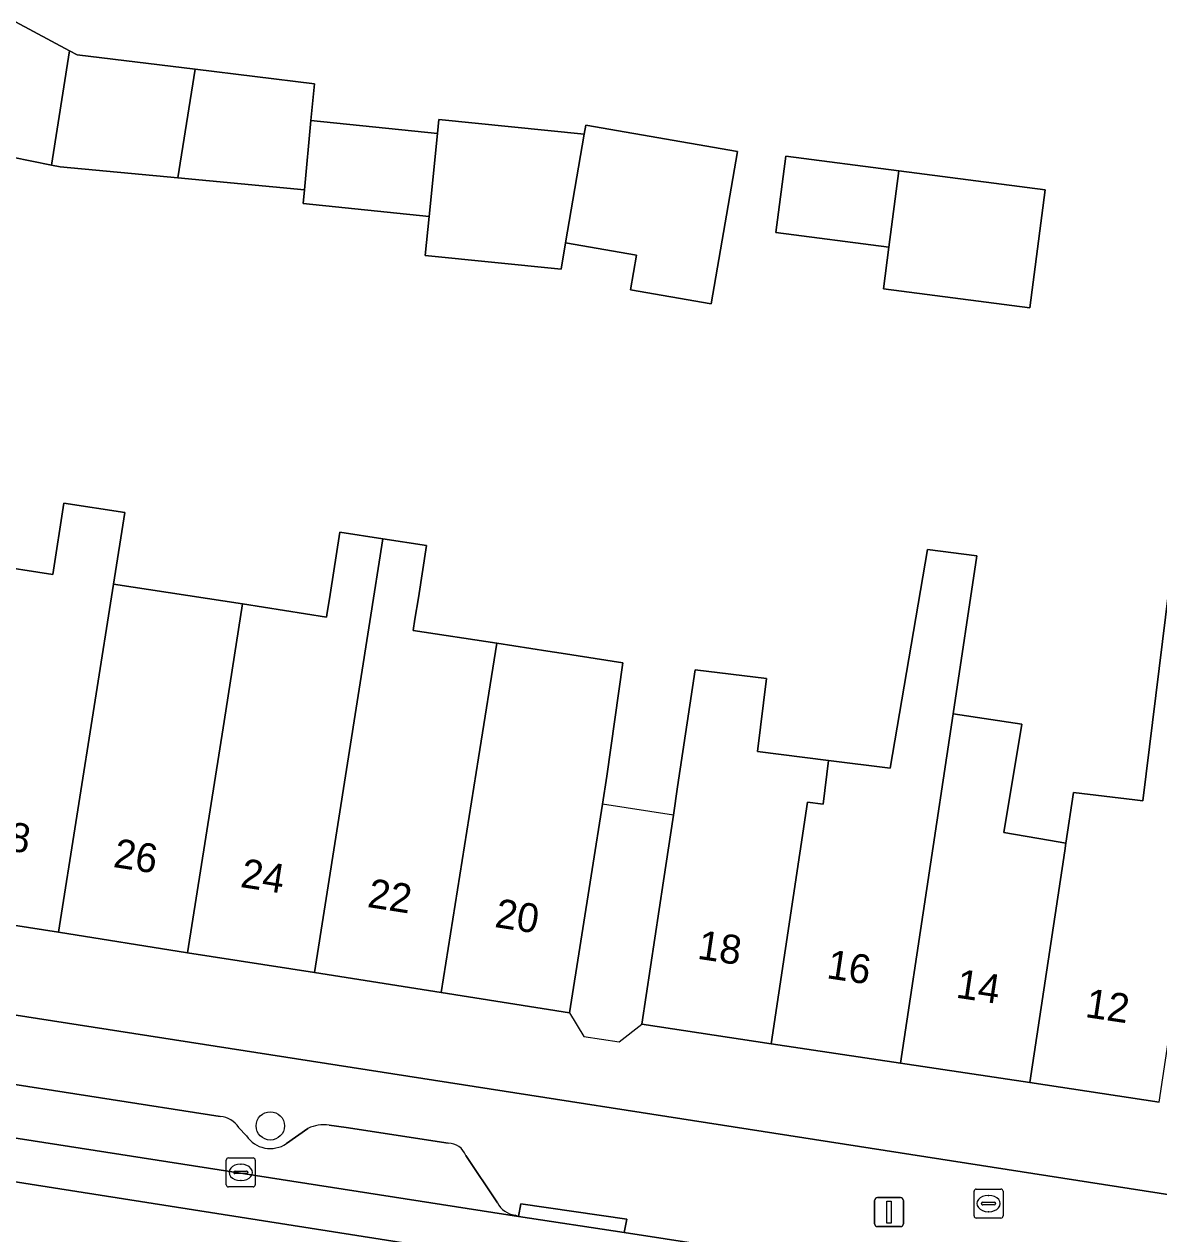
# Model space of a CAD drawing. Extents: x 162172 to 163187, y 382874 to 383685.
# Drawn here: x 162633.67 to 162672.8, y 383331.69 to 383373.42 of the extents above; entities that cross this region are included whole.
import ezdxf

# ---------------------------------------------------------------- set-up
doc = ezdxf.new("R2010")
doc.units = 0
for name, color, linetype in [('IMGEO_Boom', 7, 'Continuous'), ('IMGEO_Brandkraan', 7, 'Continuous'), ('IMGEO_Erf', 7, 'Continuous'), ('IMGEO_Kolk', 7, 'Continuous'), ('IMGEO_Lichtmast', 7, 'Continuous'), ('IMGEO_Pand', 7, 'Continuous'), ('IMGEO_Pand_nummerreeks', 7, 'Continuous'), ('IMGEO_Pand_overbouw', 7, 'Continuous'), ('IMGEO_Parkeervlak_open', 7, 'Continuous'), ('IMGEO_Rijbaan_lokaal_gesloten', 7, 'Continuous'), ('IMGEO_Voetpad_open', 7, 'Continuous')]:
    doc.layers.add(name, color=color, linetype=linetype)

msp = doc.modelspace()

# ---------------------------------------------------------------- linework, layer by layer
at = {"layer": 'IMGEO_Boom'}
msp.add_circle((162642.154, 383335.41), 0.489, dxfattribs=at)
at = {"layer": 'IMGEO_Brandkraan'}
for p, q in [((162666.424, 383332.304), (162666.424, 383333.156)), ((162666.499, 383333.23), (162667.351, 383333.23)), ((162667.425, 383333.156), (162667.425, 383332.304)), ((162666.683, 383332.724), (162666.683, 383332.736)), ((162667.121, 383332.687), (162666.723, 383332.687)), ((162666.726, 383332.773), (162667.124, 383332.773)), ((162666.912, 383333.01), (162666.937, 383333.01)), ((162667.167, 383332.736), (162667.167, 383332.724)), ((162667.351, 383332.23), (162666.499, 383332.23)), ((162666.935, 383332.45), (162666.91, 383332.45))]:
    msp.add_line(p, q, dxfattribs=at)
for points in [[(162666.424, 383332.304), (162666.424, 383333.156)], [(162666.499, 383333.23), (162667.351, 383333.23)], [(162667.425, 383333.156), (162667.425, 383332.304)], [(162667.351, 383332.23), (162666.499, 383332.23)]]:
    msp.add_lwpolyline(points, dxfattribs=at)
for centre, radius, start, end in [((162666.501, 383333.154), 0.0765, 91.552, 178.448), ((162666.501, 383333.154), 0.0765, 91.552, 178.448), ((162667.349, 383333.154), 0.0765, 1.552, 88.448), ((162667.349, 383333.154), 0.0765, 1.552, 88.448), ((162666.723, 383332.733), 0.0403, 85.8775, 175.7526), ((162666.72, 383332.723), 0.0366, 178.938, 274.7102), ((162667.124, 383332.73), 0.043, 264.8664, 352.4533), ((162667.128, 383332.735), 0.0386, 1.7309, 96.639), ((162666.501, 383332.306), 0.0765, 181.552, 268.448), ((162666.501, 383332.306), 0.0765, 181.552, 268.448), ((162667.349, 383332.306), 0.0765, 271.552, 358.448), ((162667.349, 383332.306), 0.0765, 271.552, 358.448)]:
    msp.add_arc(centre, radius, start, end, dxfattribs=at)
for centre, major_axis, ratio, start_param, end_param in [((162666.911, 383332.73), (-0.387, 0.002), 0.722429, 4.712389, 7.853982), ((162666.936, 383332.73), (-0.39, 0.002), 0.717154, 1.570796, 4.712389)]:
    msp.add_ellipse(centre, major_axis=major_axis, ratio=ratio, start_param=start_param, end_param=end_param, dxfattribs=at)
at = {"layer": 'IMGEO_Erf'}
for points in [[(162657.355, 383363.773), (162654.579, 383364.252), (162654.786, 383365.449), (162652.337, 383365.872), (162652.18, 383364.963), (162647.493, 383365.442), (162647.63, 383366.787), (162643.29, 383367.231), (162643.334, 383367.707), (162638.969, 383368.115), (162634.911, 383368.495), (162634.612, 383368.556), (162630.529, 383369.385), (162631.35, 383374.589), (162635.235, 383372.503), (162635.493, 383372.364), (162639.563, 383371.863), (162643.675, 383371.357), (162643.557, 383370.091), (162647.922, 383369.645), (162647.972, 383370.133), (162652.984, 383369.621), (162653.038, 383369.931), (162658.262, 383369.029)], [(162668.352, 383363.634), (162663.296, 383364.291), (162663.483, 383365.725), (162659.593, 383366.23), (162659.935, 383368.867), (162663.826, 383368.361), (162668.881, 383367.704)]]:
    msp.add_lwpolyline(points, close=True, dxfattribs=at)
for points in [[(162632.43, 383354.782), (162634.653, 383354.438), (162635.034, 383356.898), (162637.141, 383356.572), (162636.75, 383354.103), (162641.194, 383353.415), (162644.093, 383352.966), (162644.104, 383353.036), (162644.216, 383353.742), (162644.555, 383355.896), (162646.035, 383355.667), (162647.545, 383355.433), (162647.261, 383353.63), (162647.144, 383352.888), (162647.083, 383352.503), (162649.963, 383352.058), (162651.73, 383351.784), (162652.182, 383351.714), (162654.308, 383351.385), (162653.761, 383347.48), (162653.608, 383346.505), (162653.253, 383344.252), (162652.476, 383339.312), (162648.053, 383340.008), (162643.675, 383340.698), (162639.301, 383341.386), (162634.846, 383342.088), (162630.546, 383342.765)], [(162672.811, 383336.231), (162668.35, 383336.902), (162663.891, 383337.573), (162659.431, 383338.243), (162654.971, 383338.914), (162655.715, 383343.859), (162656.055, 383346.125), (162656.202, 383347.105), (162656.81, 383351.144), (162659.272, 383350.84), (162658.96, 383348.322), (162661.408, 383348.019), (162663.53, 383347.756), (162664.816, 383355.293), (162666.525, 383355.081), (162665.704, 383349.623), (162668.072, 383349.267), (162667.447, 383345.529), (162668.997, 383345.262), (162669.592, 383345.16), (162669.856, 383346.915), (162671.969, 383346.653), (162672.244, 383346.619), (162673.262, 383354.819)], [(162625.697, 383340.429), (162681.225, 383331.781)]]:
    msp.add_lwpolyline(points, dxfattribs=at)
at = {"layer": 'IMGEO_Kolk'}
for p, q in [((162640.636, 383333.381), (162640.636, 383334.233)), ((162640.711, 383334.307), (162641.563, 383334.307)), ((162641.124, 383334.087), (162641.149, 383334.087)), ((162641.637, 383334.233), (162641.637, 383333.381)), ((162640.895, 383333.801), (162640.895, 383333.813)), ((162641.333, 383333.764), (162640.935, 383333.764)), ((162640.938, 383333.85), (162641.336, 383333.85)), ((162641.147, 383333.527), (162641.122, 383333.527)), ((162641.379, 383333.813), (162641.379, 383333.801)), ((162641.563, 383333.307), (162640.711, 383333.307))]:
    msp.add_line(p, q, dxfattribs=at)
for points in [[(162640.636, 383333.381), (162640.636, 383334.233)], [(162640.711, 383334.307), (162641.563, 383334.307)], [(162641.637, 383334.233), (162641.637, 383333.381)], [(162641.563, 383333.307), (162640.711, 383333.307)]]:
    msp.add_lwpolyline(points, dxfattribs=at)
for centre, radius, start, end in [((162640.713, 383334.231), 0.0765, 91.552, 178.448), ((162640.713, 383334.231), 0.0765, 91.552, 178.448), ((162641.561, 383334.231), 0.0765, 1.552, 88.448), ((162641.561, 383334.231), 0.0765, 1.552, 88.448), ((162640.935, 383333.81), 0.0403, 85.8775, 175.7526), ((162640.932, 383333.8), 0.0366, 178.938, 274.7102), ((162641.336, 383333.807), 0.043, 264.8664, 352.4533), ((162641.34, 383333.812), 0.0386, 1.7309, 96.639), ((162640.713, 383333.383), 0.0765, 181.552, 268.448), ((162640.713, 383333.383), 0.0765, 181.552, 268.448), ((162641.561, 383333.383), 0.0765, 271.552, 358.448), ((162641.561, 383333.383), 0.0765, 271.552, 358.448)]:
    msp.add_arc(centre, radius, start, end, dxfattribs=at)
for centre, major_axis, ratio, start_param, end_param in [((162641.123, 383333.807), (-0.387, 0.002), 0.722429, 4.712389, 7.853982), ((162641.148, 383333.807), (-0.39, 0.002), 0.717154, 1.570796, 4.712389)]:
    msp.add_ellipse(centre, major_axis=major_axis, ratio=ratio, start_param=start_param, end_param=end_param, dxfattribs=at)
at = {"layer": 'IMGEO_Lichtmast'}
for p, q in [((162662.996, 383332.034), (162662.996, 383332.834)), ((162662.996, 383332.834), (162662.996, 383332.034)), ((162663.096, 383332.934), (162663.886, 383332.934)), ((162663.886, 383332.934), (162663.096, 383332.934)), ((162663.986, 383332.834), (162663.986, 383332.034)), ((162663.986, 383332.034), (162663.986, 383332.834)), ((162663.886, 383331.934), (162663.096, 383331.934)), ((162663.096, 383331.934), (162663.886, 383331.934))]:
    msp.add_line(p, q, dxfattribs=at)
msp.add_lwpolyline([(162663.416, 383332.809), (162663.566, 383332.809), (162663.566, 383332.059), (162663.416, 383332.059), (162663.416, 383332.809)], dxfattribs=at)
for centre, start, end in [((162663.096, 383332.834), 90, 180), ((162663.096, 383332.834), 90, 180), ((162663.886, 383332.834), 0, 90), ((162663.886, 383332.834), 360, 90), ((162663.096, 383332.034), 180, 270), ((162663.096, 383332.034), 180, 270), ((162663.886, 383332.034), 270, 0), ((162663.886, 383332.034), 270, 0)]:
    msp.add_arc(centre, 0.1, start, end, dxfattribs=at)
at = {"layer": 'IMGEO_Pand'}
for points in [[(162634.612, 383368.556), (162635.235, 383372.503), (162631.35, 383374.589), (162630.529, 383369.385)], [(162638.969, 383368.115), (162639.563, 383371.863), (162635.493, 383372.364), (162635.235, 383372.503), (162634.612, 383368.556), (162634.911, 383368.495)], [(162643.557, 383370.091), (162643.675, 383371.357), (162639.563, 383371.863), (162638.969, 383368.115), (162643.334, 383367.707)], [(162647.922, 383369.645), (162643.557, 383370.091), (162643.334, 383367.707), (162643.29, 383367.231), (162647.63, 383366.787)], [(162652.984, 383369.621), (162647.972, 383370.133), (162647.922, 383369.645), (162647.63, 383366.787), (162647.493, 383365.442), (162652.18, 383364.963), (162652.337, 383365.872)], [(162658.262, 383369.029), (162653.038, 383369.931), (162652.984, 383369.621), (162652.337, 383365.872), (162654.786, 383365.449), (162654.579, 383364.252), (162657.355, 383363.773)], [(162663.826, 383368.361), (162659.935, 383368.867), (162659.593, 383366.23), (162663.483, 383365.725)], [(162663.826, 383368.361), (162663.483, 383365.725), (162663.296, 383364.291), (162668.352, 383363.634), (162668.881, 383367.704)], [(162674.624, 383348.282), (162675.443, 383353.731), (162676.222, 383358.91), (162674.187, 383359.162), (162673.954, 383359.191), (162673.807, 383359.209), (162673.775, 383358.952), (162673.706, 383358.396), (162673.262, 383354.819), (162672.244, 383346.619), (162671.969, 383346.653), (162669.856, 383346.915), (162669.592, 383345.16), (162669.553, 383344.9), (162668.35, 383336.902), (162672.811, 383336.231)], [(162636.75, 383354.103), (162637.141, 383356.572), (162635.034, 383356.898), (162634.653, 383354.438), (162632.43, 383354.782), (162631.805, 383350.75), (162630.546, 383342.765), (162634.846, 383342.088)], [(162641.194, 383353.415), (162640.565, 383349.363), (162639.301, 383341.386), (162643.675, 383340.698), (162645.584, 383352.806), (162646.035, 383355.667), (162644.555, 383355.896), (162644.216, 383353.742), (162644.104, 383353.036), (162644.093, 383352.966)], [(162649.963, 383352.058), (162647.083, 383352.503), (162647.144, 383352.888), (162647.261, 383353.63), (162647.545, 383355.433), (162646.035, 383355.667), (162645.584, 383352.806), (162643.675, 383340.698), (162648.053, 383340.008), (162649.337, 383348.109)], [(162665.704, 383349.623), (162666.525, 383355.081), (162664.816, 383355.293), (162663.53, 383347.756), (162661.408, 383348.019), (162661.221, 383346.511), (162660.684, 383346.577), (162659.431, 383338.243), (162663.891, 383337.573)], [(162641.194, 383353.415), (162636.75, 383354.103), (162634.846, 383342.088), (162639.301, 383341.386), (162640.565, 383349.363)], [(162653.608, 383346.505), (162653.761, 383347.48), (162654.308, 383351.385), (162652.182, 383351.714), (162651.73, 383351.784), (162649.963, 383352.058), (162649.337, 383348.109), (162648.053, 383340.008), (162652.476, 383339.312), (162653.253, 383344.252)], [(162660.684, 383346.577), (162661.221, 383346.511), (162661.408, 383348.019), (162658.96, 383348.322), (162659.272, 383350.84), (162656.81, 383351.144), (162656.202, 383347.105), (162656.055, 383346.125), (162655.715, 383343.859), (162654.971, 383338.914), (162659.431, 383338.243)], [(162669.592, 383345.16), (162668.997, 383345.262), (162667.447, 383345.529), (162668.072, 383349.267), (162665.704, 383349.623), (162663.891, 383337.573), (162668.35, 383336.902), (162669.553, 383344.9)]]:
    msp.add_lwpolyline(points, close=True, dxfattribs=at)
at = {"layer": 'IMGEO_Pand_overbouw'}
msp.add_lwpolyline([(162655.715, 383343.859), (162656.055, 383346.125), (162653.608, 383346.505), (162653.253, 383344.252), (162652.476, 383339.312), (162652.967, 383338.498), (162654.186, 383338.306), (162654.971, 383338.914)], close=True, dxfattribs=at)
at = {"layer": 'IMGEO_Parkeervlak_open'}
for points in [[(162613.69, 383338.058), (162650.713, 383332.282), (162650.594, 383332.335)], [(162640.43, 383335.732), (162632.157, 383337.021)], [(162641.333, 383335.071), (162641.064, 383335.355)], [(162643.454, 383335.322), (162642.708, 383334.797)], [(162648.288, 383334.814), (162644.777, 383335.356), (162644.18, 383335.43)], [(162649.992, 383332.761), (162648.894, 383334.388)]]:
    msp.add_lwpolyline(points, dxfattribs=at)
for centre, radius, start, end in [((162640.363, 383334.898), 0.837, 33.1104, 85.4151), ((162643.982, 383334.27), 1.177, 80.2887, 116.6339), ((162642.156, 383335.614), 0.986, 213.4051, 304.0552), ((162648.296, 383334.182), 0.632, 19.0306, 90.7572), ((162650.681, 383333.096), 0.766, 205.9303, 263.5001)]:
    msp.add_arc(centre, radius, start, end, dxfattribs=at)
at = {"layer": 'IMGEO_Rijbaan_lokaal_gesloten'}
for points in [[(162701.209, 383324.364), (162695.256, 383325.416), (162667.234, 383329.74), (162654.358, 383331.729), (162650.713, 383332.282), (162613.69, 383338.058), (162613.319, 383338.115), (162605.204, 383339.371), (162601.788, 383339.9), (162574.971, 383344.078), (162574.184, 383344.194), (162573.598, 383344.329), (162573.305, 383344.396)], [(162759.102, 383279.436), (162751.245, 383288.934), (162744.614, 383296.969), (162741.887, 383300.164), (162738.772, 383303.437), (162735.656, 383306.164), (162728.412, 383311.307), (162722.803, 383314.892), (162719.766, 383316.606), (162716.105, 383318.242), (162707.381, 383321.359), (162706.089, 383321.777), (162704.23, 383322.378), (162698.267, 383323.385), (162686.155, 383325.334), (162667.305, 383328.139), (162627.21, 383334.45)], [(162627.21, 383334.45), (162667.305, 383328.139), (162686.155, 383325.334), (162698.267, 383323.385), (162704.23, 383322.378), (162706.089, 383321.777), (162707.381, 383321.359), (162716.105, 383318.242), (162719.766, 383316.606), (162722.803, 383314.892), (162728.412, 383311.307), (162735.656, 383306.164), (162738.772, 383303.437), (162741.887, 383300.164), (162744.614, 383296.969), (162751.245, 383288.934), (162759.102, 383279.436)]]:
    msp.add_lwpolyline(points, dxfattribs=at)
at = {"layer": 'IMGEO_Voetpad_open'}
for points in [[(162707.156, 383322.944), (162707.317, 383323.417), (162714.458, 383320.909), (162714.598, 383324.993), (162710.992, 383326.273), (162707.584, 383327.496), (162694.994, 383329.543), (162690.373, 383330.294), (162686.082, 383330.991), (162681.225, 383331.781), (162625.697, 383340.429)], [(162632.157, 383337.021), (162640.43, 383335.732)], [(162641.064, 383335.355), (162641.333, 383335.071)], [(162642.708, 383334.797), (162643.454, 383335.322)], [(162644.18, 383335.43), (162644.777, 383335.356), (162648.288, 383334.814)], [(162648.894, 383334.388), (162649.992, 383332.761)], [(162650.594, 383332.335), (162650.713, 383332.282), (162650.798, 383332.721), (162654.447, 383332.19), (162654.358, 383331.729), (162667.234, 383329.74)]]:
    msp.add_lwpolyline(points, dxfattribs=at)
msp.add_lwpolyline([(162654.358, 383331.729), (162654.447, 383332.19), (162650.798, 383332.721), (162650.713, 383332.282)], close=True, dxfattribs=at)
for centre, radius, start, end in [((162640.363, 383334.898), 0.837, 33.1104, 85.4151), ((162643.982, 383334.27), 1.177, 80.2887, 116.6339), ((162642.156, 383335.614), 0.986, 213.4051, 304.0552), ((162648.296, 383334.182), 0.632, 19.0306, 90.7572), ((162650.681, 383333.096), 0.766, 205.9303, 263.5001)]:
    msp.add_arc(centre, radius, start, end, dxfattribs=at)

# ---------------------------------------------------------------- texts
at = {"layer": 'IMGEO_Pand_nummerreeks'}
for s, rotation, p in [('28', 351.0504, (162632.328, 383345.035)), ('26', 351.0504, (162636.709, 383344.346)), ('24', 351.0504, (162641.092, 383343.656)), ('22', 351.0504, (162645.473, 383342.966)), ('20', 351.0504, (162649.863, 383342.275)), ('18', 351.4457, (162656.852, 383341.18)), ('16', 351.4457, (162661.309, 383340.51)), ('14', 351.4457, (162665.769, 383339.839)), ('12', 351.4457, (162670.226, 383339.169))]:
    msp.add_text(s, height=1, rotation=rotation, dxfattribs=at).set_placement(p)

doc.saveas('drawing.dxf')
